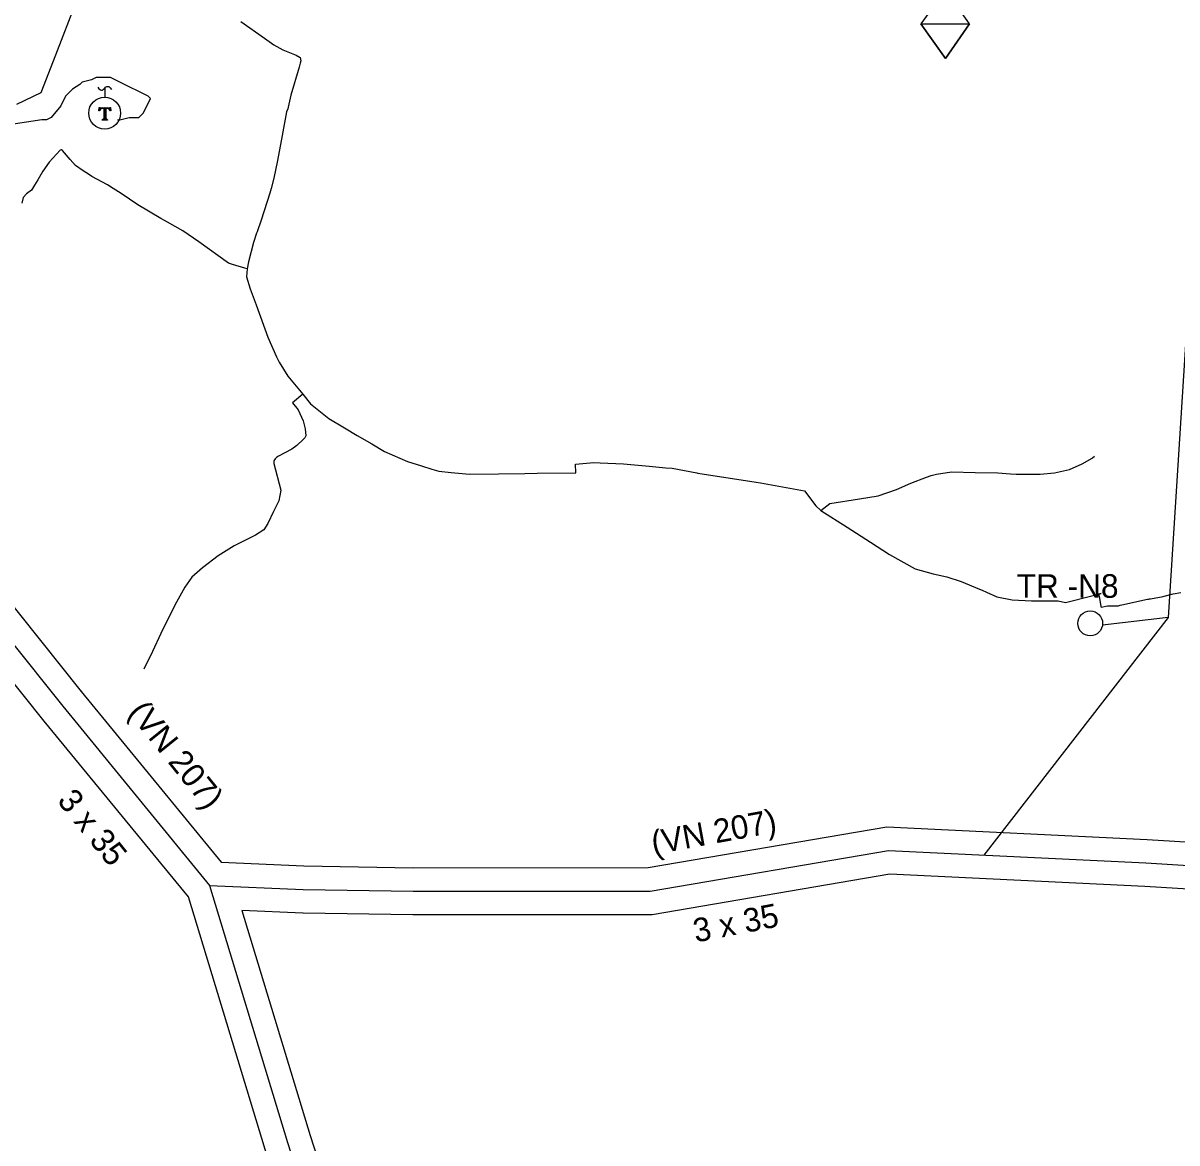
# Model space of a CAD drawing. Extents: x -439095 to -431527, y -1129525 to -1119219.
# Drawn here: x -437672.9 to -437184.8, y -1124403.8 to -1123930 of the extents above; entities that cross this region are included whole.
import ezdxf

# ---------------------------------------------------------------- set-up
doc = ezdxf.new("R2010")
doc.units = 0
for name, color, linetype in [('13861012_venkovní vedení elektrické sítě VN 1-35 kV_Stav', 7, 'Continuous'), ('14250012_plynovod STL_Stav', 7, 'Continuous'), ('14801013_OP vedení elektrické sítě_Stav', 7, 'Continuous'), ('Vrstva 13', 7, 'Continuous'), ('Vrstva 19', 7, 'Continuous'), ('Vrstva 21', 7, 'Continuous'), ('Vrstva 57', 7, 'Continuous'), ('Vrstva 58', 7, 'Continuous'), ('Vrstva 59', 7, 'Continuous')]:
    doc.layers.add(name, color=color, linetype=linetype)

msp = doc.modelspace()

# ---------------------------------------------------------------- linework, layer by layer
at = {"layer": '13861012_venkovní vedení elektrické sítě VN 1-35 kV_Stav'}
msp.add_line((-437188.49, -1124181.49), (-437216.29, -1124184.71), dxfattribs=at)
for points in [[(-437129.37, -1123686.51), (-437093.81, -1123746.85), (-437142.42, -1123876.3), (-437179.57, -1124041.51), (-437188.49, -1124181.49), (-437266.5, -1124282.08)], [(-438263.63, -1123828.96), (-438072.97, -1123875.97), (-437977.31, -1123900.59), (-437935.03, -1123912.96), (-437886.52, -1123939.93), (-437886.48, -1123940.09), (-437848.4, -1123976.82), (-437836.05, -1123992.37), (-437836.05, -1123992.37), (-437821.56, -1124011.34), (-437777.52, -1124066.05), (-437725.21, -1124132.8), (-437656.19, -1124219.09), (-437594.04, -1124294.91), (-437554.42, -1124296.58), (-437554.42, -1124296.58), (-437507.95, -1124297.38), (-437407.71, -1124297.33), (-437306.88, -1124280.12), (-437197.9, -1124285.4), (-437107.85, -1124290.93)], [(-437594.04, -1124294.91), (-437561.06, -1124403.71), (-437532.02, -1124493.84), (-437512.18, -1124558.05), (-437465.26, -1124644.76), (-437423.07, -1124724.23), (-437376.49, -1124809.95), (-437340.25, -1124878.04), (-437300.21, -1124952.35), (-437264.2, -1125019.77), (-437218.58, -1125105.97), (-437178.17, -1125179.18), (-437127.47, -1125244.74), (-437060.46, -1125309.51), (-436996.4, -1125371.43), (-436937.2, -1125428.24), (-436916.22, -1125475.49), (-436894.84, -1125522.87), (-436894.84, -1125522.87), (-436875.66, -1125567.39), (-436875.41, -1125567.39), (-436875.41, -1125567.49)]]:
    msp.add_lwpolyline(points, dxfattribs=at)
at = {"layer": '14250012_plynovod STL_Stav'}
for points in [[(-437675.59, -1123964.37), (-437665.26, -1123959.36), (-437659.16, -1123943.4), (-437650.52, -1123921.14)], [(-437580.82, -1123929.39), (-437570.87, -1123936.44), (-437566.9, -1123939.22), (-437563.06, -1123941.33), (-437557.43, -1123943.56), (-437555.77, -1123944.64), (-437555.48, -1123945.98), (-437555.67, -1123946.98), (-437556.17, -1123948.64), (-437556.17, -1123948.65), (-437559.72, -1123960.55), (-437560.79, -1123965.6), (-437561.01, -1123966.28), (-437561.46, -1123967.57), (-437563.35, -1123977.55), (-437565.32, -1123988.15), (-437566.82, -1123995.6), (-437567.98, -1124000), (-437568.49, -1124001.95), (-437572.25, -1124013.41), (-437573.93, -1124018.29), (-437574.15, -1124018.94), (-437575.5, -1124022.86), (-437577.52, -1124031.05), (-437578.14, -1124034), (-437578.47, -1124037.38), (-437576.87, -1124042.48), (-437574.38, -1124049.22), (-437569.35, -1124062.86), (-437565.68, -1124071.2), (-437564.57, -1124073.43), (-437560.89, -1124079.39), (-437554.64, -1124087.09), (-437551.4, -1124091.07), (-437543.66, -1124097.29), (-437537.02, -1124101.28), (-437531.58, -1124104.55), (-437525.45, -1124108.1), (-437520.03, -1124111.24), (-437510.3, -1124115.46), (-437504.38, -1124117.34), (-437500, -1124118.72), (-437497.13, -1124119.64), (-437491.79, -1124120.17), (-437484.03, -1124120.94), (-437471.79, -1124120.74), (-437460.64, -1124120.58), (-437455.45, -1124120.5), (-437439.06, -1124120.27), (-437439.21, -1124116.69), (-437431.55, -1124115.99), (-437428.77, -1124116.11), (-437418.98, -1124116.52), (-437408.07, -1124117.51), (-437401.06, -1124118.14), (-437401.05, -1124118.14), (-437398.31, -1124118.39), (-437387.92, -1124120.37), (-437387.53, -1124120.41), (-437362.82, -1124124.3), (-437360.93, -1124124.6), (-437342.43, -1124127.91), (-437337.62, -1124134.26), (-437335.4, -1124136.22), (-437324.32, -1124143.35), (-437314.51, -1124149.66), (-437306.44, -1124154.85), (-437295.53, -1124160.98), (-437287.98, -1124163.11), (-437282.21, -1124164.34), (-437276.11, -1124166.25), (-437268.28, -1124169.59), (-437267.25, -1124170.02), (-437265.42, -1124170.82), (-437260.93, -1124172.75), (-437254.44, -1124174.08), (-437246.27, -1124174.47), (-437235.07, -1124174.55), (-437231.89, -1124175.13), (-437220.77, -1124172.36), (-437218.02, -1124171.64), (-437216.92, -1124171.35), (-437218.02, -1124171.64), (-437217.75, -1124172.6), (-437217.02, -1124176.69), (-437216.82, -1124177.16), (-437214.12, -1124176.6), (-437209.54, -1124176.55), (-437209.18, -1124176.49), (-437209.19, -1124176.43), (-437208.81, -1124176.35), (-437208.16, -1124176.21), (-437197.3, -1124173.79), (-437196.9, -1124173.72), (-437196.45, -1124173.59), (-437196.38, -1124173.59), (-437196.34, -1124173.67), (-437195.98, -1124173.59), (-437190.68, -1124172.66), (-437190.2, -1124172.49), (-437186.38, -1124171.48), (-437183.09, -1124170.94)], [(-437578.14, -1124034), (-437579.08, -1124033.73), (-437584.35, -1124032.14), (-437586.04, -1124031.63), (-437598.57, -1124022.6), (-437605.41, -1124017.87), (-437611.85, -1124014.28), (-437613.07, -1124013.56), (-437614.6, -1124012.66), (-437624.42, -1124006.88), (-437631.44, -1124002.14), (-437634.81, -1124000), (-437637.18, -1123998.5), (-437643.89, -1123994.94), (-437644.43, -1123994.56), (-437646.37, -1123993.27), (-437647.54, -1123992.56), (-437650.79, -1123990.23), (-437652.99, -1123987.72), (-437656.2, -1123983.98), (-437656.65, -1123983.7), (-437657.29, -1123983.8), (-437661.87, -1123988.86), (-437664.55, -1123992.66), (-437666.71, -1123996.38), (-437668.07, -1123998.66), (-437668.96, -1124000), (-437669.43, -1124000.71), (-437671.55, -1124002.34), (-437672.94, -1124003.8), (-437673.47, -1124006.25)], [(-437554.64, -1124087.09), (-437558.9, -1124090.67), (-437556.63, -1124093.71), (-437554.43, -1124098.38), (-437553.67, -1124101.71), (-437553.36, -1124104.68), (-437553.73, -1124105.54), (-437554.27, -1124106.12), (-437557.07, -1124108.77), (-437559.22, -1124110.3), (-437564.92, -1124113.25), (-437565.69, -1124113.9), (-437566.29, -1124114.41), (-437566.81, -1124115.22), (-437566.84, -1124116.4), (-437563.88, -1124127.71), (-437564.77, -1124132.18), (-437567.06, -1124136.68), (-437569.47, -1124141.82), (-437571.1, -1124144.49), (-437574.59, -1124146.64), (-437583.66, -1124151.25), (-437590.39, -1124155.5), (-437597.05, -1124160.55), (-437601.53, -1124164.48), (-437604.54, -1124168.76), (-437608.09, -1124175.03), (-437613.88, -1124186.43), (-437619.06, -1124197.81), (-437621.57, -1124202.74), (-437621.89, -1124203.44)], [(-437335.4, -1124136.22), (-437331.62, -1124133.29), (-437319.13, -1124131.29), (-437311.24, -1124130), (-437303.51, -1124127.39), (-437297.32, -1124124.64), (-437290.69, -1124122.11), (-437288.76, -1124121.49), (-437286.56, -1124120.83), (-437280.12, -1124119.89), (-437270.14, -1124120.12), (-437260.59, -1124120.37), (-437255.27, -1124120.75), (-437252.84, -1124120.92), (-437242.64, -1124120.92), (-437236.53, -1124120.28), (-437230.3, -1124118.97), (-437224.91, -1124116.58), (-437220.66, -1124114.09), (-437220.55, -1124114.03), (-437219.65, -1124113.29)]]:
    msp.add_lwpolyline(points, dxfattribs=at)
at = {"layer": '14801013_OP vedení elektrické sítě_Stav'}
for points in [[(-437603.03, -1124299.71), (-437663.96, -1124225.38), (-437733.05, -1124139.01), (-437785.35, -1124072.27), (-437829.43, -1124017.51), (-437843.94, -1123998.52), (-437855.82, -1123983.56), (-437873.56, -1123966.44)], [(-437793.3, -1124030.5), (-437769.69, -1124059.83), (-437717.37, -1124126.59), (-437648.42, -1124212.8), (-437589.14, -1124285.11), (-437554.13, -1124286.58), (-437507.87, -1124287.38), (-437408.56, -1124287.33), (-437307.49, -1124270.08), (-437197.35, -1124275.41), (-437107.23, -1124280.95), (-436998.91, -1124287.85), (-436905.81, -1124293.56), (-436805.64, -1124300.19), (-436734.95, -1124304.81)], [(-436613.25, -1124332.22), (-436699.78, -1124327.15), (-436806.96, -1124320.15), (-436907.09, -1124313.52), (-437000.15, -1124307.81), (-437108.47, -1124300.91), (-437198.45, -1124295.39), (-437306.27, -1124290.16), (-437406.86, -1124307.33), (-437508.03, -1124307.38), (-437554.5, -1124306.58), (-437554.63, -1124306.58), (-437580.38, -1124305.49)], [(-437243, -1125081.2), (-437273.03, -1125024.46), (-437309.02, -1124957.08), (-437349.07, -1124882.76), (-437385.3, -1124814.69), (-437431.88, -1124728.96), (-437474.07, -1124649.48), (-437521.44, -1124561.94), (-437541.56, -1124496.85), (-437570.6, -1124406.69), (-437603.03, -1124299.71)], [(-437580.38, -1124305.49), (-437551.52, -1124400.73), (-437522.48, -1124490.83), (-437502.92, -1124554.16), (-437456.45, -1124640.04), (-437414.26, -1124719.5), (-437367.68, -1124805.21), (-437331.43, -1124873.32), (-437291.4, -1124947.62), (-437255.37, -1125015.08), (-437209.78, -1125101.21), (-437169.79, -1125173.67), (-437120, -1125238.05), (-437053.51, -1125302.32), (-436989.46, -1125364.23), (-436928.86, -1125422.39), (-436907.09, -1125471.4), (-436885.52, -1125519.22), (-436885.49, -1125519.31), (-436877.62, -1125537.58)]]:
    msp.add_lwpolyline(points, dxfattribs=at)
at = {"layer": 'Vrstva 19'}
msp.add_circle((-437221.49, -1124184.03), 5.25, dxfattribs=at)
at = {"layer": 'Vrstva 57'}
for p, q in [((-437638.43, -1123957.62), (-437638.43, -1123961.37)), ((-437640.51, -1123966.94), (-437640.85, -1123966.6)), ((-437640.17, -1123966.57), (-437640.79, -1123965.96)), ((-437639.83, -1123966.21), (-437640.15, -1123965.88)), ((-437639.12, -1123966.21), (-437639.45, -1123965.88)), ((-437637.98, -1123966.64), (-437638.74, -1123965.88)), ((-437637.98, -1123967.35), (-437638.71, -1123966.62)), ((-437637.98, -1123968.06), (-437638.71, -1123967.33)), ((-437637.98, -1123968.76), (-437638.71, -1123968.04)), ((-437637.98, -1123969.47), (-437638.71, -1123968.74)), ((-437637.98, -1123970.18), (-437638.71, -1123969.45)), ((-437637.7, -1123966.21), (-437638.03, -1123965.88)), ((-437637, -1123966.21), (-437637.32, -1123965.88)), ((-437635.83, -1123966.67), (-437636.62, -1123965.88)), ((-437635.91, -1123965.88), (-437636.02, -1123965.77)), ((-437639.16, -1123971.12), (-437639.39, -1123970.89)), ((-437638.45, -1123971.12), (-437639, -1123970.57)), ((-437637.74, -1123971.12), (-437638.71, -1123970.16))]:
    msp.add_line(p, q, dxfattribs=at)
msp.add_lwpolyline([(-437641.34, -1123957.18), (-437640.83, -1123957.81), (-437640.17, -1123958.31), (-437639.78, -1123958.43), (-437639.38, -1123958.36), (-437638.86, -1123958.05), (-437638.43, -1123957.62), (-437638.01, -1123957.19), (-437637.49, -1123956.88), (-437637.09, -1123956.81), (-437636.7, -1123956.93), (-437636.04, -1123957.43), (-437635.53, -1123958.07)], dxfattribs=at)
msp.add_lwpolyline([(-437635.92, -1123965.77), (-437635.78, -1123967.16), (-437635.96, -1123967.16), (-437636.84, -1123966.21), (-437637.98, -1123966.21), (-437637.98, -1123970.33), (-437637.23, -1123970.94), (-437637.23, -1123971.12), (-437639.45, -1123971.12), (-437639.45, -1123970.94), (-437638.71, -1123970.33), (-437638.71, -1123966.21), (-437639.85, -1123966.21), (-437640.72, -1123967.16), (-437640.91, -1123967.16), (-437640.77, -1123965.77), (-437640.58, -1123965.77), (-437640.26, -1123965.88), (-437636.43, -1123965.88), (-437636.11, -1123965.77)], close=True, dxfattribs=at)
msp.add_circle((-437638.43, -1123968.12), 6.75, dxfattribs=at)
at = {"layer": 'Vrstva 58'}
msp.add_lwpolyline([(-437633, -1123971), (-437632, -1123971), (-437628, -1123970), (-437624, -1123970), (-437623, -1123969), (-437622, -1123968), (-437619, -1123962), (-437620, -1123961), (-437632, -1123955), (-437636, -1123953), (-437638, -1123953), (-437640, -1123953), (-437642, -1123953), (-437644, -1123954), (-437648, -1123955), (-437649, -1123956), (-437652, -1123958), (-437655, -1123961), (-437657, -1123965), (-437661, -1123970), (-437661, -1123970), (-437663, -1123971), (-437665, -1123971), (-437678, -1123973)], dxfattribs=at)
at = {"layer": 'Vrstva 59'}
for points in [[(-437282.67, -1123915.77), (-437293.09, -1123930.33), (-437282.67, -1123944.96), (-437272.61, -1123930.33)], [(-437293.09, -1123930.33), (-437272.61, -1123930.33), (-437282.67, -1123944.96)]]:
    msp.add_lwpolyline(points, close=True, dxfattribs=at)

# ---------------------------------------------------------------- texts
at = {"layer": 'Vrstva 13'}
for s, rotation, p in [('(VN 207)', 308.8716, (-437628.8, -1124221.86)), ('3 x 35', 308.8714, (-437658.85, -1124259.19)), ('(VN 207)', 10.3558, (-437406.2, -1124281.91)), ('3 x 35', 10.9321, (-437388.41, -1124319.08))]:
    msp.add_text(s, height=10, rotation=rotation, dxfattribs=at).set_placement(p)
at = {"layer": 'Vrstva 21'}
msp.add_text('TR -N8', height=10, dxfattribs=at).set_placement((-437252.59, -1124173.21))

doc.saveas('drawing.dxf')
